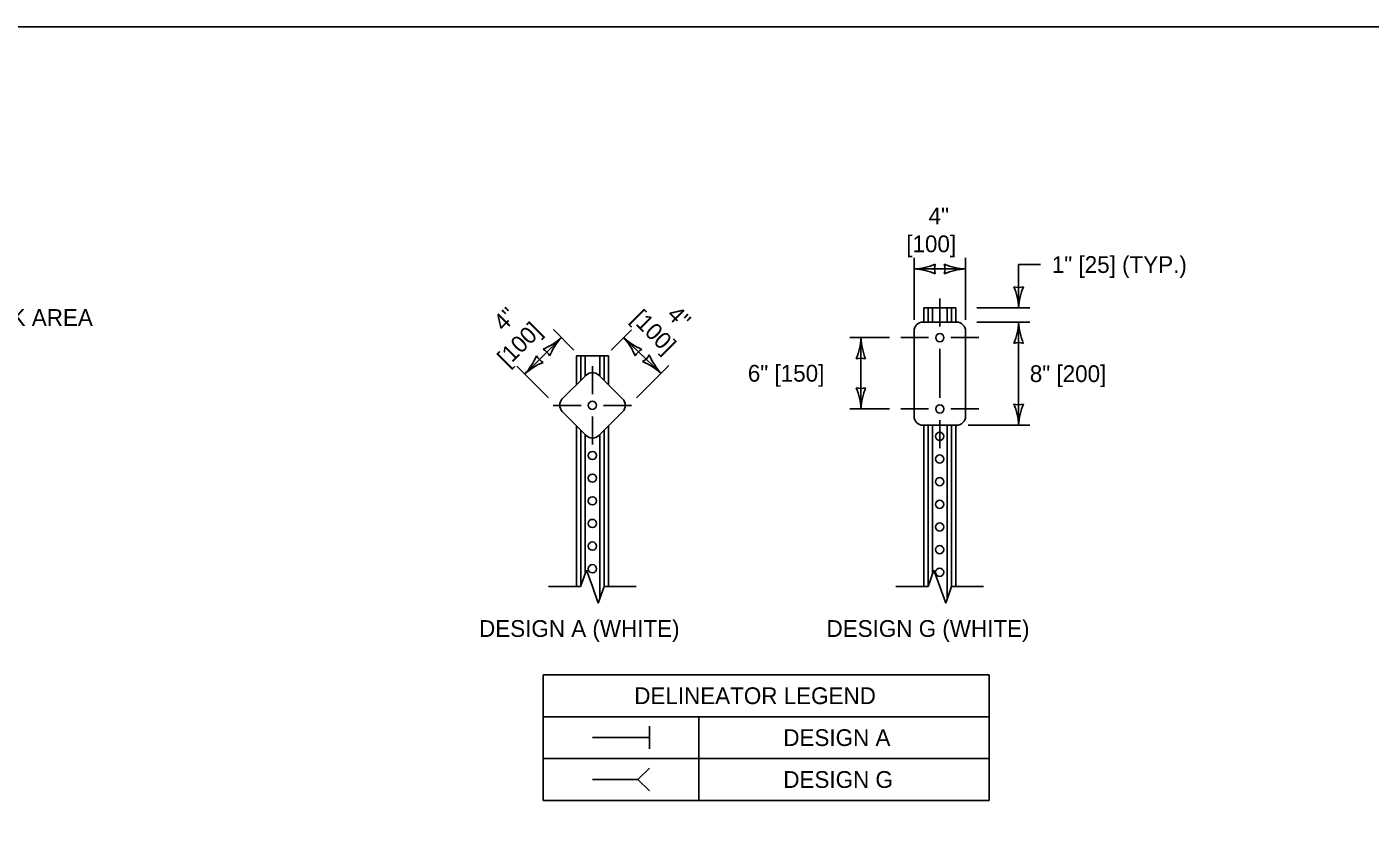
# Model space of a CAD drawing. Extents: x 49991.4 to 50021, y 49987.6 to 50011.4.
# Drawn here: x 50003.867 to 50008.676, y 49996.174 to 49998.999 of the extents above; entities that cross this region are included whole.
import ezdxf

# ---------------------------------------------------------------- set-up
doc = ezdxf.new("R2010")
doc.units = 0
for name, color, linetype in [('Level 1', 7, 'Continuous'), ('Level 2', 7, 'Continuous'), ('Level 3', 7, 'Continuous'), ('Level 5', 7, 'Continuous'), ('Level 6', 7, 'Continuous')]:
    doc.layers.add(name, color=color, linetype=linetype)

msp = doc.modelspace()

# ---------------------------------------------------------------- linework, layer by layer
at = {"layer": 'Level 1'}
for p, q in [((50007.0782, 49997.9425), (50007.0782, 49997.9932)), ((50007.0782, 49997.9932), (50007.192, 49997.9932)), ((50007.0934, 49997.9425), (50007.0934, 49997.9932)), ((50007.1089, 49997.9425), (50007.1089, 49997.9932)), ((50007.1614, 49997.9425), (50007.1614, 49997.9932)), ((50007.1768, 49997.9425), (50007.1768, 49997.9932)), ((50007.192, 49997.9426), (50007.192, 49997.9932)), ((50007.0753, 49997.9426), (50007.195, 49997.9426)), ((50007.0428, 49997.9103), (50007.0428, 49997.6055)), ((50007.2273, 49997.9103), (50007.2273, 49997.6055)), ((50005.8344, 49997.7193), (50005.8344, 49997.8217)), ((50005.8344, 49997.8217), (50005.9486, 49997.8217)), ((50005.8496, 49997.734), (50005.8496, 49997.8217)), ((50005.8652, 49997.7489), (50005.8652, 49997.8217)), ((50005.9177, 49997.7489), (50005.9177, 49997.8217)), ((50005.9331, 49997.7357), (50005.9331, 49997.8217)), ((50005.9486, 49997.7193), (50005.9486, 49997.8217)), ((50005.7837, 49997.6677), (50005.8688, 49997.7525)), ((50005.9994, 49997.6675), (50005.9144, 49997.7525)), ((50005.8688, 49997.537), (50005.7837, 49997.6221)), ((50005.9145, 49997.537), (50005.9994, 49997.6217)), ((50005.9994, 49997.6217), (50005.9994, 49997.6217)), ((50005.8344, 49996.9957), (50005.8344, 49997.5695)), ((50005.8496, 49996.9963), (50005.8496, 49997.5558)), ((50005.9331, 49996.9943), (50005.9331, 49997.554)), ((50005.9486, 49996.9957), (50005.9486, 49997.5705)), ((50007.0753, 49997.5732), (50007.195, 49997.5732)), ((50007.0782, 49996.9957), (50007.0782, 49997.5732)), ((50007.0934, 49996.9963), (50007.0934, 49997.5732)), ((50007.1089, 49997.0401), (50007.1089, 49997.5732)), ((50007.1614, 49996.9504), (50007.1614, 49997.5732)), ((50007.1768, 49996.994), (50007.1768, 49997.5732)), ((50007.192, 49996.9957), (50007.192, 49997.5732)), ((50005.8652, 49997.0404), (50005.8652, 49997.5411)), ((50005.9177, 49996.9507), (50005.9177, 49997.5396)), ((50006.0954, 49996.4146), (50006.0954, 49996.4958)), ((50006.0954, 49996.4552), (50005.8916, 49996.4552)), ((50006.0544, 49996.3052), (50005.8916, 49996.3052)), ((50006.0954, 49996.3458), (50006.0544, 49996.3052)), ((50006.0954, 49996.2642), (50006.0544, 49996.3052))]:
    msp.add_line(p, q, dxfattribs=at)
msp.add_lwpolyline([(49999.3835, 49998.9992), (50016.7501, 49998.9992), (50016.7501, 49987.7988), (49999.3835, 49987.7988)], close=True, dxfattribs=at)
for centre in [(50007.1351, 49997.8868), (50005.8913, 49997.6444), (50007.1351, 49997.6317), (50007.1347, 49997.5335), (50005.8915, 49997.465), (50007.1347, 49997.4525), (50005.8915, 49997.3839), (50007.1347, 49997.3714), (50005.8915, 49997.3028), (50007.1347, 49997.2903), (50005.8915, 49997.2218), (50007.1347, 49997.2092), (50005.8915, 49997.1407), (50007.1347, 49997.1282), (50005.8915, 49997.0596), (50007.1347, 49997.0471)]:
    msp.add_circle(centre, 0.0147, dxfattribs=at)
for centre, start, end in [((50007.0751, 49997.9102), 90, 180), ((50007.1952, 49997.9102), 0, 90), ((50005.8916, 49997.7296), 45, 135), ((50005.8066, 49997.6448), 135, 225), ((50005.9766, 49997.6446), 314.8931, 45), ((50007.0751, 49997.6055), 180, 270), ((50007.1952, 49997.6055), 270, 0), ((50005.8917, 49997.5597), 225, 315)]:
    msp.add_arc(centre, 0.0323, start, end, dxfattribs=at)
at = {"layer": 'Level 2'}
for p, q in [((50005.7148, 49996.6802), (50007.3122, 49996.6802)), ((50005.7148, 49996.2302), (50005.7148, 49996.6802)), ((50007.3122, 49996.6802), (50007.3122, 49996.2302)), ((50005.7148, 49996.5302), (50007.3122, 49996.5302)), ((50006.2722, 49996.2302), (50006.2722, 49996.5302)), ((50005.7148, 49996.3802), (50007.3122, 49996.3802)), ((50005.7148, 49996.2302), (50007.3122, 49996.2302))]:
    msp.add_line(p, q, dxfattribs=at)
at = {"layer": 'Level 3'}
for p, q in [((50007.0428, 49997.9502), (50007.0428, 49998.1726)), ((50007.0428, 49998.1326), (50007.2273, 49998.1326)), ((50007.2273, 49997.9502), (50007.2273, 49998.1726)), ((50007.4173, 49998.1484), (50007.4961, 49998.1484)), ((50007.4173, 49997.9932), (50007.4173, 49998.1484)), ((50007.2673, 49997.993), (50007.4573, 49997.9932)), ((50007.2673, 49997.9425), (50007.4573, 49997.9425)), ((50007.4173, 49997.5732), (50007.4173, 49997.9425)), ((50005.825, 49997.8423), (50005.7521, 49997.9154)), ((50005.9583, 49997.842), (50006.0315, 49997.9151)), ((50005.6496, 49997.7567), (50005.7804, 49997.8871)), ((50006.0032, 49997.8869), (50006.137, 49997.7593)), ((50006.8128, 49997.8868), (50006.9551, 49997.8868)), ((50006.8528, 49997.6317), (50006.8528, 49997.8868)), ((50005.7343, 49997.6717), (50005.6214, 49997.785)), ((50006.0489, 49997.6712), (50006.1653, 49997.7876)), ((50006.8128, 49997.6317), (50006.9551, 49997.6317)), ((50007.2369, 49997.5732), (50007.4573, 49997.5732))]:
    msp.add_line(p, q, dxfattribs=at)
for centre, radius, start, end in [((50007.0313, 49998.3653), 0.233, 272.8273, 292.0772), ((50007.0337, 49997.9105), 0.2223, 67.456, 87.6395), ((50007.171, 49998.1326), 0.0548, 162.1388, 197.8612), ((50007.2365, 49998.3547), 0.2223, 247.456, 267.6395), ((50007.0991, 49998.1326), 0.0548, 342.1388, 17.8612), ((50007.2388, 49997.8999), 0.233, 92.8273, 112.0772), ((50007.4173, 49998.1214), 0.0548, 252.1388, 287.8612), ((50007.1846, 49997.9817), 0.233, 2.8273, 22.0772), ((50007.6395, 49997.984), 0.2223, 157.456, 177.6395), ((50007.1952, 49997.9517), 0.2223, 337.456, 357.6395), ((50007.65, 49997.954), 0.233, 182.8273, 202.0772), ((50005.6301, 49998.0509), 0.2223, 292.3683, 312.5518), ((50005.6896, 49997.7966), 0.0548, 27.0511, 62.7734), ((50005.9529, 49997.7304), 0.233, 137.7396, 156.9894), ((50005.8396, 49997.7363), 0.2223, 22.456, 42.6395), ((50006.1596, 49998.0595), 0.233, 227.8273, 247.0772), ((50006.0938, 49997.7962), 0.0548, 117.1388, 152.8612), ((50006.6307, 49997.896), 0.2223, 337.456, 357.6395), ((50007.0855, 49997.8983), 0.233, 182.8273, 202.0772), ((50007.4173, 49997.8143), 0.0548, 72.1388, 107.8612), ((50005.4772, 49997.9134), 0.233, 317.7396, 336.9894), ((50005.8, 49997.5929), 0.2223, 112.3683, 132.5518), ((50005.7404, 49997.8472), 0.0548, 207.0511, 242.7734), ((50006.0464, 49997.85), 0.0548, 297.1388, 332.8612), ((50005.9806, 49997.5866), 0.233, 47.8273, 67.0772), ((50006.3006, 49997.9099), 0.2223, 202.456, 222.6395), ((50006.8528, 49997.7586), 0.0548, 72.1388, 107.8612), ((50006.8528, 49997.7599), 0.0548, 252.1388, 287.8612), ((50006.6201, 49997.6202), 0.233, 2.8273, 22.0772), ((50007.075, 49997.6225), 0.2223, 157.456, 177.6395), ((50007.4173, 49997.7014), 0.0548, 252.1388, 287.8612), ((50007.1846, 49997.5617), 0.233, 2.8273, 22.0772), ((50007.6395, 49997.564), 0.2223, 157.456, 177.6395)]:
    msp.add_arc(centre, radius, start, end, dxfattribs=at)
at = {"layer": 'Level 5'}
for p, q in [((50007.1351, 49997.9268), (50007.1351, 49998.0268)), ((50006.9951, 49997.8868), (50007.0951, 49997.8868)), ((50007.1351, 49997.6717), (50007.1351, 49997.8468)), ((50007.1751, 49997.8868), (50007.2751, 49997.8868)), ((50005.8913, 49997.6844), (50005.8913, 49997.7844)), ((50005.8513, 49997.6444), (50005.7513, 49997.6444)), ((50005.8913, 49997.6044), (50005.8913, 49997.5044)), ((50005.9313, 49997.6444), (50006.0313, 49997.6444)), ((50006.9951, 49997.6317), (50007.0951, 49997.6317)), ((50007.1751, 49997.6317), (50007.2751, 49997.6317)), ((50007.1351, 49997.4917), (50007.1351, 49997.5917))]:
    msp.add_line(p, q, dxfattribs=at)
at = {"layer": 'Level 6'}
for p, q in [((50005.8704, 49997.0551), (50005.8494, 49996.9957)), ((50005.8704, 49997.0551), (50005.8915, 49996.9957)), ((50007.1142, 49997.0551), (50007.0932, 49996.9957)), ((50007.1142, 49997.0551), (50007.1353, 49996.9957)), ((50005.7344, 49996.9957), (50005.8494, 49996.9957)), ((50005.8915, 49996.9957), (50005.9126, 49996.9363)), ((50005.9336, 49996.9957), (50005.9126, 49996.9363)), ((50005.9336, 49996.9957), (50006.0486, 49996.9957)), ((50006.9782, 49996.9957), (50007.0932, 49996.9957)), ((50007.1353, 49996.9957), (50007.1564, 49996.9363)), ((50007.1774, 49996.9957), (50007.1564, 49996.9363)), ((50007.1774, 49996.9957), (50007.292, 49996.9957))]:
    msp.add_line(p, q, dxfattribs=at)

# ---------------------------------------------------------------- texts
at = {"layer": 'Level 2'}
for s, p in [('4"', (50007.0949, 49998.2926)), ('[100]', (50007.015, 49998.1926)), ('1" [25] (TYP.)', (50007.5361, 49998.1184)), ('WORK AREA', (50003.6127, 49997.929)), ('6" [150]', (50006.4479, 49997.7293)), ('8" [200]', (50007.4573, 49997.7279)), ('DESIGN A (WHITE)', (50005.4858, 49996.8157)), ('DESIGN G (WHITE)', (50006.7296, 49996.8157)), ('DELINEATOR LEGEND', (50006.0413, 49996.5752)), ('DESIGN A', (50006.5749, 49996.4252)), ('DESIGN G', (50006.5749, 49996.2752))]:
    msp.add_text(s, height=0.06, dxfattribs=at).set_placement(p)
for s, rotation, p in [('4"', 44.8988, (50005.5736, 49997.9068)), ('[100]', 315, (50006.0276, 49997.9504)), ('4"', 315, (50006.1548, 49997.9647)), ('[100]', 44.8988, (50005.5876, 49997.7796))]:
    msp.add_text(s, height=0.06, rotation=rotation, dxfattribs=at).set_placement(p)

doc.saveas('drawing.dxf')
